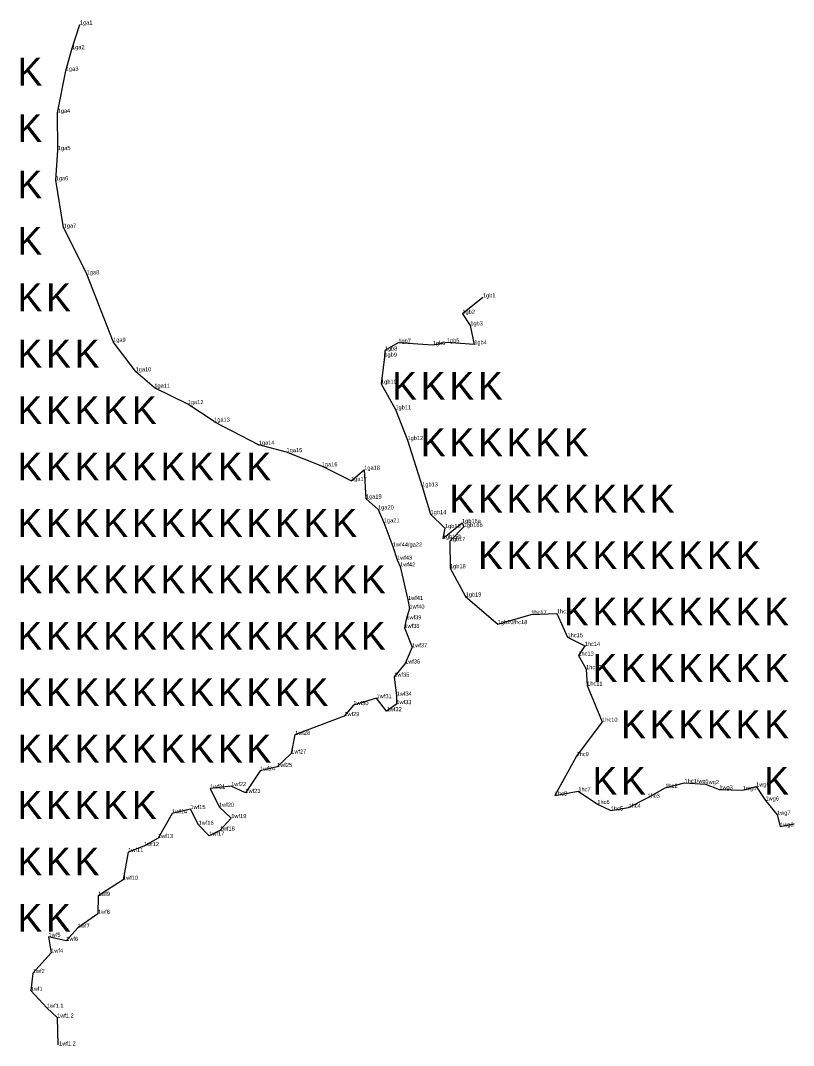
# Model space of a CAD drawing. Extents: x 2072529 to 2268812, y 436423 to 470008.
# Drawn here: x 2076782 to 2077727, y 466236 to 467490 of the extents above; entities that cross this region are included whole.
import ezdxf

# ---------------------------------------------------------------- set-up
doc = ezdxf.new("R2010")
doc.units = 0
for name, color, linetype in [('Old_Level_20', 7, 'Continuous'), ('Old_Level_52', 7, 'Continuous'), ('Old_Level_55', 7, 'Continuous'), ('Old_Level_60', 7, 'Continuous')]:
    doc.layers.add(name, color=color, linetype=linetype)

msp = doc.modelspace()

# ---------------------------------------------------------------- linework, layer by layer
at = {"layer": 'Old_Level_20'}
for p, q in [((2076854.65, 467484.78), (2076854.65, 467484.78)), ((2076844.954, 467454.704), (2076844.954, 467454.704)), ((2076837.497, 467428.251), (2076837.497, 467428.251)), ((2076827.391, 467376.85), (2076827.391, 467376.85)), ((2076827.762, 467331.339), (2076827.762, 467331.339)), ((2076825.08, 467294.331), (2076825.08, 467294.331)), ((2076834.707, 467236.383), (2076834.707, 467236.383)), ((2076863.032, 467179.351), (2076863.032, 467179.351)), ((2077347.518, 467151.076), (2077347.518, 467151.076)), ((2077322.361, 467131.009), (2077322.361, 467131.009)), ((2077332.018, 467116.785), (2077332.018, 467116.785)), ((2076895.224, 467096.823), (2076895.224, 467096.823)), ((2077303.405, 467096.026), (2077303.405, 467096.026)), ((2077227.426, 467086.093), (2077227.426, 467086.093)), ((2077244.017, 467095.476), (2077244.017, 467095.476)), ((2077286.071, 467092.796), (2077286.071, 467092.796)), ((2077336.897, 467093.676), (2077336.897, 467093.676)), ((2077226.936, 467078.499), (2077226.936, 467078.499)), ((2076922.723, 467060.575), (2076922.723, 467060.575)), ((2076945.626, 467040.67), (2076945.626, 467040.67)), ((2077222.892, 467045.424), (2077222.892, 467045.424)), ((2076986.557, 467020.556), (2076986.557, 467020.556)), ((2077240.488, 467014.148), (2077240.488, 467014.148)), ((2077018.785, 466999.108), (2077018.785, 466999.108)), ((2077073.244, 466970.876), (2077073.244, 466970.876)), ((2077255.175, 466976.512), (2077255.175, 466976.512)), ((2077107.34, 466961.796), (2077107.34, 466961.796)), ((2077150.43, 466944.464), (2077150.43, 466944.464)), ((2077202.316, 466940.323), (2077202.316, 466940.323)), ((2077186.273, 466926.576), (2077186.273, 466926.576)), ((2077273.219, 466919.851), (2077273.219, 466919.851)), ((2077204.404, 466905.081), (2077204.404, 466905.081)), ((2077219.257, 466891.841), (2077219.257, 466891.841)), ((2077283.468, 466885.932), (2077283.468, 466885.932)), ((2077226.361, 466875.879), (2077226.361, 466875.879)), ((2077321.96, 466875.185), (2077321.96, 466875.185)), ((2077324.06, 466870.281), (2077324.06, 466870.281)), ((2077301.082, 466868.863), (2077301.082, 466868.863)), ((2077237.424, 466846.396), (2077237.424, 466846.396)), ((2077298.298, 466855.989), (2077298.298, 466855.989)), ((2077306.858, 466853.106), (2077306.858, 466853.106)), ((2077242.518, 466830.259), (2077242.518, 466830.259)), ((2077246.174, 466822.008), (2077246.174, 466822.008)), ((2077307.231, 466819.801), (2077307.231, 466819.801)), ((2077326.348, 466785.22), (2077326.348, 466785.22)), ((2077255.857, 466781.05), (2077255.857, 466781.05)), ((2077257.643, 466770.402), (2077257.643, 466770.402)), ((2077253.786, 466757.289), (2077253.786, 466757.289)), ((2077406.607, 466763.275), (2077406.607, 466763.275)), ((2077438.007, 466764.604), (2077438.007, 466764.604)), ((2077251.432, 466746.746), (2077251.432, 466746.746)), ((2077365.665, 466751.422), (2077365.665, 466751.422)), ((2077450.913, 466735.364), (2077450.913, 466735.364)), ((2077260.849, 466723.069), (2077260.849, 466723.069)), ((2077471.918, 466724.786), (2077471.918, 466724.786)), ((2077464.212, 466712.941), (2077464.212, 466712.941)), ((2077252.282, 466703.239), (2077252.282, 466703.239)), ((2077473.617, 466696.267), (2077473.617, 466696.267)), ((2077239.067, 466687.138), (2077239.067, 466687.138)), ((2077474.962, 466676.267), (2077474.962, 466676.267)), ((2077217.439, 466660.749), (2077217.439, 466660.749)), ((2077241.975, 466663.89), (2077241.975, 466663.89)), ((2077189.09, 466652.343), (2077189.09, 466652.343)), ((2077229.756, 466644.926), (2077229.756, 466644.926)), ((2077241.616, 466653.55), (2077241.616, 466653.55)), ((2077177.969, 466638.897), (2077177.969, 466638.897)), ((2077493.276, 466632.098), (2077493.276, 466632.098)), ((2077117.629, 466615.98), (2077117.629, 466615.98)), ((2077113.012, 466593.076), (2077113.012, 466593.076)), ((2077462.006, 466589.959), (2077462.006, 466589.959)), ((2077074.971, 466572.145), (2077074.971, 466572.145)), ((2077095.703, 466576.7), (2077095.703, 466576.7)), ((2077594.039, 466557.128), (2077594.039, 466557.128)), ((2077013.861, 466550.319), (2077013.861, 466550.319)), ((2077039.575, 466553.32), (2077039.575, 466553.32)), ((2077056.967, 466544.952), (2077056.967, 466544.952)), ((2077464.158, 466546.938), (2077464.158, 466546.938)), ((2077570.523, 466551.188), (2077570.523, 466551.188)), ((2077619.696, 466555.7), (2077619.696, 466555.7)), ((2077636.568, 466549.246), (2077636.568, 466549.246)), ((2077665.191, 466548.313), (2077665.191, 466548.313)), ((2077681.54, 466552.78), (2077681.54, 466552.78)), ((2077435.451, 466541.825), (2077435.451, 466541.825)), ((2077548.844, 466539.06), (2077548.844, 466539.06)), ((2077693.054, 466535.677), (2077693.054, 466535.677)), ((2076967.275, 466519.884), (2076967.275, 466519.884)), ((2076989.798, 466525.245), (2076989.798, 466525.245)), ((2077024.739, 466528.054), (2077024.739, 466528.054)), ((2077487.482, 466531.377), (2077487.482, 466531.377)), ((2077503.942, 466523.467), (2077503.942, 466523.467)), ((2077525.515, 466526.993), (2077525.515, 466526.993)), ((2077039.748, 466514.131), (2077039.748, 466514.131)), ((2077707.159, 466518.232), (2077707.159, 466518.232)), ((2076999.775, 466506.042), (2076999.775, 466506.042)), ((2077025.615, 466498.926), (2077025.615, 466498.926)), ((2077710.931, 466503.755), (2077710.931, 466503.755)), ((2076950.14, 466489.763), (2076950.14, 466489.763)), ((2077012.772, 466492.663), (2077012.772, 466492.663)), ((2076913.742, 466472.642), (2076913.742, 466472.642)), ((2076932.84, 466479.902), (2076932.84, 466479.902)), ((2076907.376, 466438.703), (2076907.376, 466438.703)), ((2076876.785, 466419.062), (2076876.785, 466419.062)), ((2076876.676, 466397.1), (2076876.676, 466397.1)), ((2076816.305, 466368.921), (2076816.305, 466368.921)), ((2076852.053, 466379.974), (2076852.053, 466379.974)), ((2076837.94, 466364.017), (2076837.94, 466364.017)), ((2076819.444, 466349.571), (2076819.444, 466349.571)), ((2076797.011, 466324.608), (2076797.011, 466324.608)), ((2076794.423, 466303.134), (2076794.423, 466303.134)), ((2076814.201, 466282.27), (2076814.201, 466282.27)), ((2076826.735, 466270.152), (2076826.735, 466270.152)), ((2076827.538, 466236.837), (2076827.538, 466236.837))]:
    msp.add_line(p, q, dxfattribs=at)
at = {"layer": 'Old_Level_52'}
for p, q in [((2076827.411, 467376.95), (2076837.489, 467428.211)), ((2076827.762, 467331.339), (2076827.392, 467376.749)), ((2076863.012, 467179.391), (2076834.773, 467236.249)), ((2076895.173, 467096.953), (2076863.048, 467179.309)), ((2076922.66, 467060.657), (2076895.308, 467096.712)), ((2076945.528, 467040.755), (2076922.801, 467060.507)), ((2076986.498, 467020.585), (2076945.743, 467040.613)), ((2077018.74, 466999.138), (2076986.611, 467020.52)), ((2077073.147, 466970.926), (2077018.833, 466999.083)), ((2077107.281, 466961.812), (2077073.35, 466970.848))]:
    msp.add_line(p, q, dxfattribs=at)
for points in [[(2076837.508, 467428.29), (2076844.954, 467454.704), (2076854.65, 467484.78)], [(2076834.683, 467236.53), (2076825.08, 467294.331), (2076827.762, 467331.339)], [(2077347.518, 467151.076), (2077322.361, 467131.009), (2077332.018, 467116.785), (2077336.897, 467093.676), (2077303.405, 467096.026), (2077286.071, 467092.796), (2077244.017, 467095.476), (2077227.426, 467086.093), (2077226.936, 467078.499), (2077222.892, 467045.424), (2077240.488, 467014.148), (2077255.175, 466976.512), (2077273.219, 466919.851), (2077283.468, 466885.932), (2077301.082, 466868.863), (2077298.298, 466855.989), (2077321.96, 466875.185), (2077324.06, 466870.281), (2077306.858, 466853.106), (2077307.231, 466819.801), (2077326.348, 466785.22), (2077365.665, 466751.422), (2077406.607, 466763.275), (2077438.007, 466764.604), (2077450.913, 466735.364), (2077471.918, 466724.786), (2077464.212, 466712.941), (2077473.617, 466696.267), (2077474.962, 466676.267), (2077493.276, 466632.098), (2077462.006, 466589.959), (2077435.451, 466541.825), (2077464.158, 466546.938), (2077487.482, 466531.377), (2077503.942, 466523.467), (2077525.515, 466526.993), (2077548.844, 466539.06), (2077570.523, 466551.188), (2077594.039, 466557.128), (2077619.696, 466555.7), (2077636.568, 466549.246), (2077665.191, 466548.313), (2077681.54, 466552.78), (2077693.054, 466535.677), (2077707.159, 466518.232), (2077710.931, 466503.755), (2077727.975, 466507.145)], [(2077186.273, 466926.576), (2077150.43, 466944.464), (2077107.397, 466961.773)], [(2077186.273, 466926.576), (2077202.316, 466940.323), (2077204.404, 466905.081), (2077219.257, 466891.841), (2077226.361, 466875.879), (2077237.424, 466846.396), (2077242.518, 466830.259), (2077246.174, 466822.008), (2077255.857, 466781.05), (2077257.643, 466770.402), (2077253.786, 466757.289), (2077251.432, 466746.746), (2077260.849, 466723.069), (2077252.282, 466703.239), (2077239.067, 466687.138), (2077241.975, 466663.89), (2077241.616, 466653.55), (2077229.756, 466644.926), (2077217.439, 466660.749), (2077189.09, 466652.343), (2077177.969, 466638.897), (2077117.629, 466615.98), (2077113.012, 466593.076), (2077095.703, 466576.7), (2077074.971, 466572.145), (2077056.967, 466544.952), (2077039.575, 466553.32), (2077013.861, 466550.319), (2077024.739, 466528.054), (2077039.748, 466514.131), (2077025.615, 466498.926), (2077012.772, 466492.663), (2076999.775, 466506.042), (2076989.798, 466525.245), (2076967.275, 466519.884), (2076950.14, 466489.763), (2076932.84, 466479.902), (2076913.742, 466472.642), (2076907.376, 466438.703), (2076876.785, 466419.062), (2076876.676, 466397.1), (2076852.053, 466379.974), (2076837.94, 466364.017), (2076816.305, 466368.921), (2076819.444, 466349.571), (2076797.011, 466324.608), (2076794.423, 466303.134)], [(2076794.423, 466303.134), (2076814.201, 466282.27), (2076826.735, 466270.152), (2076827.538, 466236.837)]]:
    msp.add_lwpolyline(points, dxfattribs=at)
for centre, start, end in [((2076838.47, 467428.019), 164.257058, 168.876897), ((2076828.392, 467376.757), 168.876897, 180.467058), ((2076835.669, 467236.694), 189.432497, 206.411339), ((2076862.117, 467178.946), 21.309447, 26.411339), ((2076896.105, 467097.316), 201.309447, 217.185225), ((2076923.457, 467061.262), 217.185225, 229.006092), ((2076946.184, 467041.51), 229.006092, 243.829928), ((2076986.057, 467019.687), 56.355908, 63.829928), ((2077019.294, 466999.971), 236.355908, 242.5974), ((2077073.607, 466971.814), 242.5974, 255.087831), ((2077107.024, 466960.845), 68.088633, 75.087831)]:
    msp.add_arc(centre, 1, start, end, dxfattribs=at)

# ---------------------------------------------------------------- texts
at = {"layer": 'Old_Level_55'}
for p in [(2076778.253, 467410.183), (2076778.253, 467341.183), (2076778.253, 467272.183), (2076778.253, 467203.183), (2076778.253, 467134.183), (2076813.253, 467134.183), (2076778.253, 467065.183), (2076813.253, 467065.183), (2076848.253, 467065.183), (2077236.487, 467025.857), (2077271.487, 467025.857), (2077306.487, 467025.857), (2077341.487, 467025.857), (2076778.253, 466996.183), (2076813.253, 466996.183), (2076848.253, 466996.183), (2076883.253, 466996.183), (2076918.253, 466996.183), (2077271.487, 466956.857), (2077306.487, 466956.857), (2077341.487, 466956.857), (2077376.487, 466956.857), (2077411.487, 466956.857), (2077446.487, 466956.857), (2076778.253, 466927.183), (2076813.253, 466927.183), (2076848.253, 466927.183), (2076883.253, 466927.183), (2076918.253, 466927.183), (2076953.253, 466927.183), (2076988.253, 466927.183), (2077023.253, 466927.183), (2077058.253, 466927.183), (2077306.487, 466887.857), (2077341.487, 466887.857), (2077376.487, 466887.857), (2077411.487, 466887.857), (2077446.487, 466887.857), (2077481.487, 466887.857), (2077516.487, 466887.857), (2077551.487, 466887.857), (2076778.253, 466858.183), (2076813.253, 466858.183), (2076848.253, 466858.183), (2076883.253, 466858.183), (2076918.253, 466858.183), (2076953.253, 466858.183), (2076988.253, 466858.183), (2077023.253, 466858.183), (2077058.253, 466858.183), (2077093.253, 466858.183), (2077128.253, 466858.183), (2077163.253, 466858.183), (2077341.487, 466818.857), (2077376.487, 466818.857), (2077411.487, 466818.857), (2077446.487, 466818.857), (2077481.487, 466818.857), (2077516.487, 466818.857), (2077551.487, 466818.857), (2077586.487, 466818.857), (2077621.487, 466818.857), (2077656.487, 466818.857), (2076778.253, 466789.183), (2076813.253, 466789.183), (2076848.253, 466789.183), (2076883.253, 466789.183), (2076918.253, 466789.183), (2076953.253, 466789.183), (2076988.253, 466789.183), (2077023.253, 466789.183), (2077058.253, 466789.183), (2077093.253, 466789.183), (2077128.253, 466789.183), (2077163.253, 466789.183), (2077198.253, 466789.183), (2077446.487, 466749.857), (2077481.487, 466749.857), (2077516.487, 466749.857), (2077551.487, 466749.857), (2077586.487, 466749.857), (2077621.487, 466749.857), (2077656.487, 466749.857), (2077691.487, 466749.857), (2076778.253, 466720.183), (2076813.253, 466720.183), (2076848.253, 466720.183), (2076883.253, 466720.183), (2076918.253, 466720.183), (2076953.253, 466720.183), (2076988.253, 466720.183), (2077023.253, 466720.183), (2077058.253, 466720.183), (2077093.253, 466720.183), (2077128.253, 466720.183), (2077163.253, 466720.183), (2077198.253, 466720.183), (2077481.487, 466680.857), (2077516.487, 466680.857), (2077551.487, 466680.857), (2077586.487, 466680.857), (2077621.487, 466680.857), (2077656.487, 466680.857), (2077691.487, 466680.857), (2076778.253, 466651.183), (2076813.253, 466651.183), (2076848.253, 466651.183), (2076883.253, 466651.183), (2076918.253, 466651.183), (2076953.253, 466651.183), (2076988.253, 466651.183), (2077023.253, 466651.183), (2077058.253, 466651.183), (2077093.253, 466651.183), (2077128.253, 466651.183), (2077516.487, 466611.857), (2077551.487, 466611.857), (2077586.487, 466611.857), (2077621.487, 466611.857), (2077656.487, 466611.857), (2077691.487, 466611.857), (2076778.253, 466582.183), (2076813.253, 466582.183), (2076848.253, 466582.183), (2076883.253, 466582.183), (2076918.253, 466582.183), (2076953.253, 466582.183), (2076988.253, 466582.183), (2077023.253, 466582.183), (2077058.253, 466582.183), (2077481.487, 466542.857), (2077516.487, 466542.857), (2077691.487, 466542.857), (2076778.253, 466513.183), (2076813.253, 466513.183), (2076848.253, 466513.183), (2076883.253, 466513.183), (2076918.253, 466513.183), (2076778.253, 466444.183), (2076813.253, 466444.183), (2076848.253, 466444.183), (2076778.253, 466375.183), (2076813.253, 466375.183)]:
    msp.add_text('K', height=34, dxfattribs=at).set_placement(p)
at = {"layer": 'Old_Level_60'}
for s, p in [('1ga1', (2076854.65, 467484.78)), ('1ga2', (2076844.954, 467454.704)), ('1ga3', (2076837.497, 467428.251)), ('1ga4', (2076827.391, 467376.85)), ('1ga5', (2076827.762, 467331.339)), ('1ga6', (2076825.08, 467294.331)), ('1ga7', (2076834.707, 467236.383)), ('1ga8', (2076863.032, 467179.351)), ('1gb1', (2077347.518, 467151.076)), ('1gb2', (2077322.361, 467131.009)), ('1gb3', (2077332.018, 467116.785)), ('1ga9', (2076895.224, 467096.823)), ('1gb7', (2077244.017, 467095.476)), ('1gb6', (2077286.071, 467092.796)), ('1gb5', (2077303.405, 467096.026)), ('1gb4', (2077336.897, 467093.676)), ('1gb9', (2077226.936, 467078.499)), ('1gb8', (2077227.426, 467086.093)), ('1ga10', (2076922.723, 467060.575)), ('1ga11', (2076945.626, 467040.67)), ('1gb10', (2077222.892, 467045.424)), ('1ga12', (2076986.557, 467020.556)), ('1gb11', (2077240.488, 467014.148)), ('1ga13', (2077018.785, 466999.108)), ('1ga14', (2077073.244, 466970.876)), ('1gb12', (2077255.175, 466976.512)), ('1ga15', (2077107.34, 466961.796)), ('1ga16', (2077150.43, 466944.464)), ('1ga18', (2077202.316, 466940.323)), ('1ga17', (2077186.273, 466926.576)), ('1gb13', (2077273.219, 466919.851)), ('1ga19', (2077204.404, 466905.081)), ('1ga20', (2077219.257, 466891.841)), ('1gb14', (2077283.468, 466885.932)), ('1ga21', (2077226.361, 466875.879)), ('1gb15', (2077301.082, 466868.863)), ('1gb16a', (2077321.96, 466875.185)), ('1gb16b', (2077324.06, 466870.281)), ('1gb15b', (2077298.298, 466855.989)), ('1gb17', (2077306.858, 466853.106)), ('1wf44/ga22', (2077237.424, 466846.396)), ('1wf43', (2077242.518, 466830.259)), ('1wf42', (2077246.174, 466822.008)), ('1gb18', (2077307.231, 466819.801)), ('1wf41', (2077255.857, 466781.05)), ('1gb19', (2077326.348, 466785.22)), ('1wf40', (2077257.643, 466770.402)), ('1hc16', (2077438.007, 466764.604)), ('1wf39', (2077253.786, 466757.289)), ('1hc17', (2077406.607, 466763.275)), ('1wf38', (2077251.432, 466746.746)), ('1gb20/hc18', (2077365.665, 466751.422)), ('1hc15', (2077450.913, 466735.364)), ('1wf37', (2077260.849, 466723.069)), ('1hc14', (2077471.918, 466724.786)), ('1wf36', (2077252.282, 466703.239)), ('1hc13', (2077464.212, 466712.941)), ('1hc12', (2077473.617, 466696.267)), ('1wf35', (2077239.067, 466687.138)), ('1hc11', (2077474.962, 466676.267)), ('1wf30', (2077189.09, 466652.343)), ('1wf31', (2077217.439, 466660.749)), ('1wf33', (2077241.616, 466653.55)), ('1wf34', (2077241.975, 466663.89)), ('1wf32', (2077229.756, 466644.926)), ('1wf29', (2077177.969, 466638.897)), ('1hc10', (2077493.276, 466632.098)), ('1wf28', (2077117.629, 466615.98)), ('1wf27', (2077113.012, 466593.076)), ('1hc9', (2077462.006, 466589.959)), ('1wf25', (2077095.703, 466576.7)), ('1wf24', (2077074.971, 466572.145)), ('1wf22', (2077039.575, 466553.32)), ('1hc1/wg1', (2077594.039, 466557.128)), ('1wg2', (2077619.696, 466555.7)), ('1wg5', (2077681.54, 466552.78)), ('1wf21', (2077013.861, 466550.319)), ('1wf23', (2077056.967, 466544.952)), ('1hc8', (2077435.451, 466541.825)), ('1hc7', (2077464.158, 466546.938)), ('1hc3', (2077548.844, 466539.06)), ('1hc2', (2077570.523, 466551.188)), ('1wg3', (2077636.568, 466549.246)), ('1wg4', (2077665.191, 466548.313)), ('1wf20', (2077024.739, 466528.054)), ('1hc6', (2077487.482, 466531.377)), ('1hc4', (2077525.515, 466526.993)), ('1wg6', (2077693.054, 466535.677)), ('1wf14', (2076967.275, 466519.884)), ('1wf15', (2076989.798, 466525.245)), ('1wf19', (2077039.748, 466514.131)), ('1hc5', (2077503.942, 466523.467)), ('1wg7', (2077707.159, 466518.232)), ('1wf16', (2076999.775, 466506.042)), ('1wg8', (2077710.931, 466503.755)), ('1wf13', (2076950.14, 466489.763)), ('1wf17', (2077012.772, 466492.663)), ('1wf18', (2077025.615, 466498.926)), ('1wf12', (2076932.84, 466479.902)), ('1wf11', (2076913.742, 466472.642)), ('1wf10', (2076907.376, 466438.703)), ('1wf9', (2076876.785, 466419.062)), ('1wf8', (2076876.676, 466397.1)), ('1wf7', (2076852.053, 466379.974)), ('1wf5', (2076816.305, 466368.921)), ('1wf6', (2076837.94, 466364.017)), ('1wf4', (2076819.444, 466349.571)), ('1wf2', (2076797.011, 466324.608)), ('1wf1', (2076794.423, 466303.134)), ('1wf1.1', (2076814.201, 466282.27)), ('1wf1.2', (2076826.735, 466270.152)), ('1wf1.2', (2076829.143, 466236.034))]:
    msp.add_text(s, height=5, dxfattribs=at).set_placement(p)

doc.saveas('drawing.dxf')
